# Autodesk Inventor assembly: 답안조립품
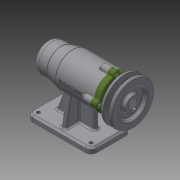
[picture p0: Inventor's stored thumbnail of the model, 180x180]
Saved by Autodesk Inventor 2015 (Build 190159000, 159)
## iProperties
Created: 2019-07
Part Number: 답안조립품
Document SubType Name: Assembly
Designer: now
Author: now
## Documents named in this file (12)
- C:\Users\now\Desktop\Choime\제비\인벤터2급\ATC) 19.07.27_시험\공용부품\답안조립품.iam
- C:\Users\now\Desktop\Choime\제비\인벤터2급\ATC) 19.07.27_시험\공용부품\V벨트풀리.ipt
- C:\Users\now\Desktop\Choime\제비\인벤터2급\ATC) 19.07.27_시험\공용부품\멈춤나사 M3.ipt
- C:\Users\now\Desktop\Choime\제비\인벤터2급\ATC) 19.07.27_시험\공용부품\베어링 6004.ipt
- C:\Users\now\Desktop\Choime\제비\인벤터2급\ATC) 19.07.27_시험\공용부품\베어링 51202.ipt
- C:\Users\now\Desktop\Choime\제비\인벤터2급\ATC) 19.07.27_시험\공용부품\본체.ipt
- C:\Users\now\Desktop\Choime\제비\인벤터2급\ATC) 19.07.27_시험\공용부품\볼트 M4.ipt
- C:\Users\now\Desktop\Choime\제비\인벤터2급\ATC) 19.07.27_시험\공용부품\어댑터슬리브.ipt
- C:\Users\now\Desktop\Choime\제비\인벤터2급\ATC) 19.07.27_시험\공용부품\오일 실.ipt
- C:\Users\now\Desktop\Choime\제비\인벤터2급\ATC) 19.07.27_시험\공용부품\축.ipt
- C:\Users\now\Desktop\Choime\제비\인벤터2급\ATC) 19.07.27_시험\공용부품\커버.ipt
- C:\Users\now\Desktop\Choime\제비\인벤터2급\ATC) 19.07.27_시험\공용부품\키 5 x 5 x 16.ipt
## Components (1 placed, 1 different names)
1. V벨트풀리:1 — 각도:2
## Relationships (1: Angle 1)
- 각도:2 [Angle]: V벨트풀리:1
